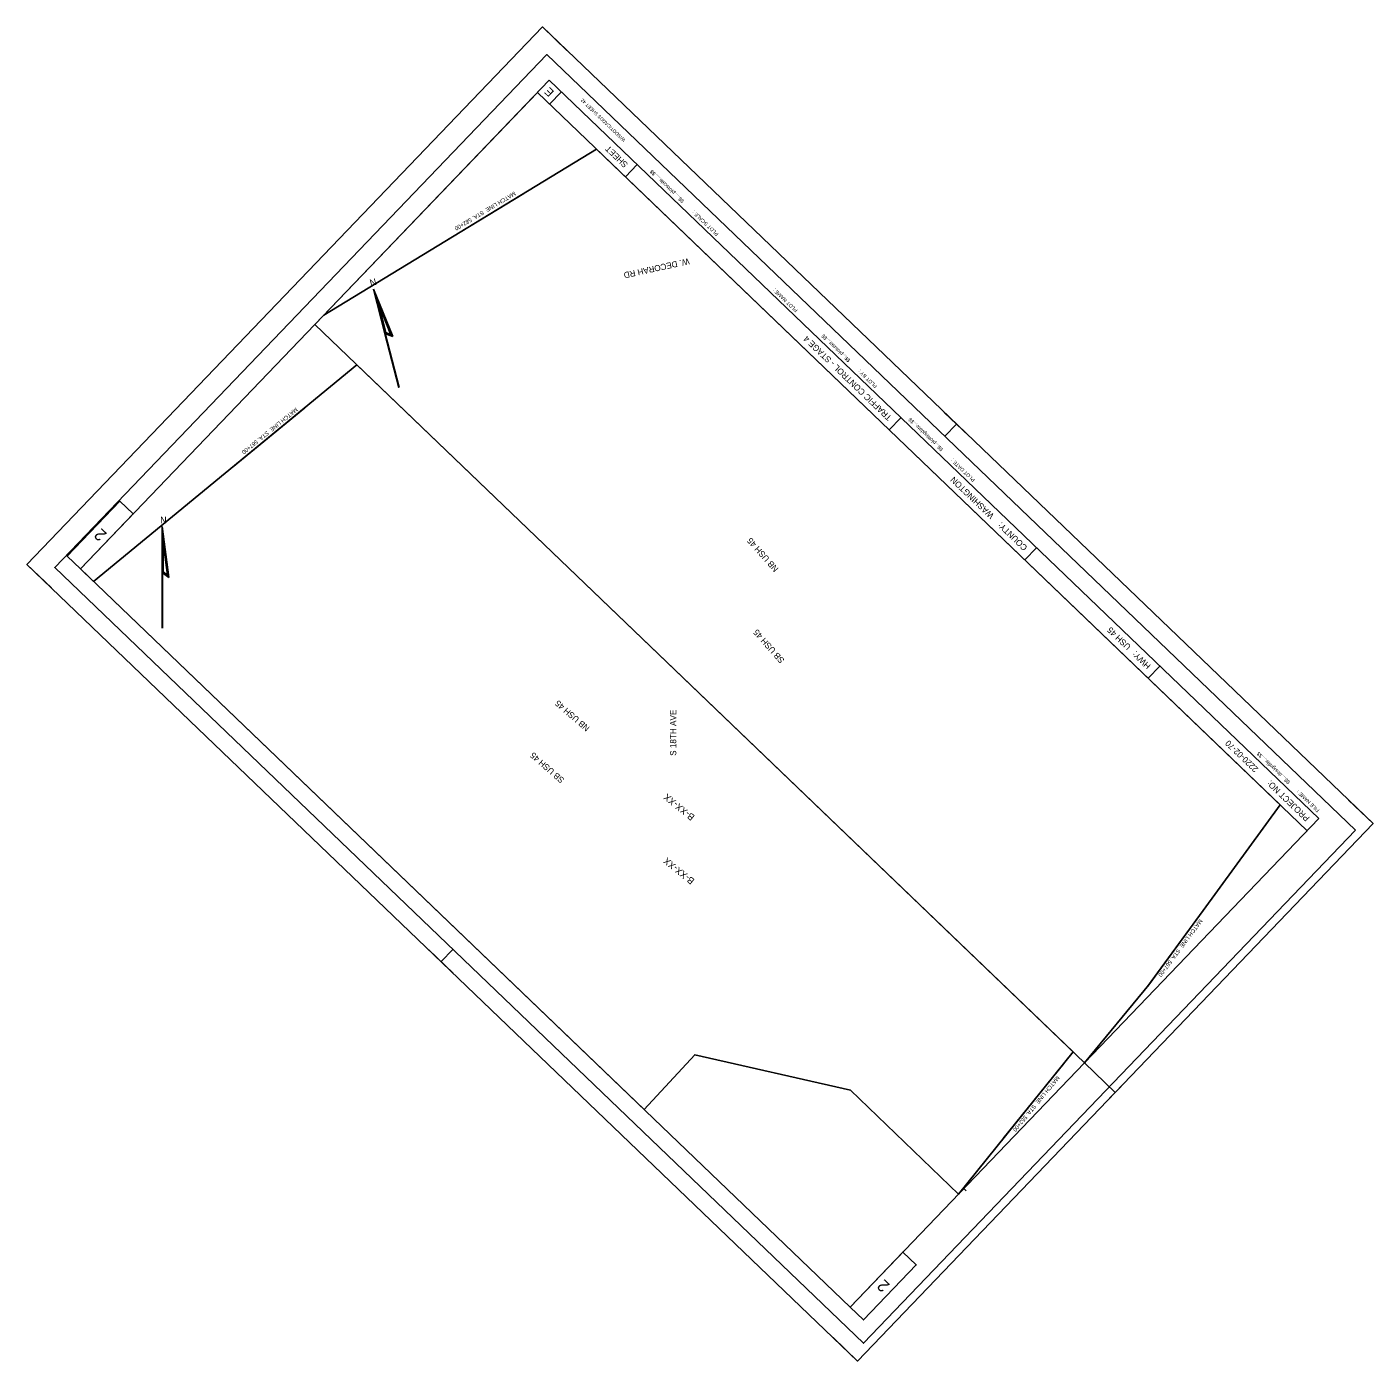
# Model space of a CAD drawing. Extents: x 356592 to 358580, y 177766 to 179737.
import ezdxf

# ---------------------------------------------------------------- set-up
doc = ezdxf.new("R2010")
doc.units = 0
for name, color, linetype in [('Default', 7, 'Continuous'), ('P_ALI_20', 7, 'Continuous'), ('P_ALI_200_Sta', 7, 'Continuous'), ('P_ALI_20_PIData', 7, 'Continuous'), ('P_ALI_20_Sta', 7, 'Continuous'), ('P_ALI_20_Tic', 7, 'Continuous'), ('P_ALI_50_Equation', 7, 'Continuous'), ('P_ALI_50_PIData', 7, 'Continuous'), ('P_ALI_50_Tic', 7, 'Continuous')]:
    doc.layers.add(name, color=color, linetype=linetype)

msp = doc.modelspace()

# ---------------------------------------------------------------- linework, layer by layer
msp.add_lwpolyline([(357818.7, 177766.2), (356591.8, 178942.9), (357353.2, 179736.8), (358580.1, 178560), (357818.7, 177766.2)])
at = {"layer": 'Default'}
for points in [[(358153.7, 178206.9), (358248.9, 178322), (358329.2, 178431.9), (358443, 178587.7), (357433, 179556.4), (357030.5, 179311.1), (357017.1, 179297.1)], [(358153.7, 178206.9), (358248.9, 178322), (358329.2, 178431.9), (358443, 178587.7), (357433, 179556.4), (357030.5, 179311.1), (357017.1, 179297.1)], [(358153.7, 178206.9), (358248.9, 178322), (358329.2, 178431.9), (358443, 178587.7), (357433, 179556.4), (357030.5, 179311.1), (357017.1, 179297.1)], [(358137, 178222.9), (357967.6, 178012.8), (357808, 178166.2), (357578.1, 178218.7), (357503.7, 178137.6), (356671, 178936.3), (356690.3, 178917.7), (357079.1, 179237.6)], [(358137, 178222.9), (357967.6, 178012.8), (357808, 178166.2), (357578.1, 178218.7), (357503.7, 178137.6), (356671, 178936.3), (356690.3, 178917.7), (357079.1, 179237.6)], [(358137, 178222.9), (357967.6, 178012.8), (357808, 178166.2), (357578.1, 178218.7), (357503.7, 178137.6), (356671, 178936.3), (356690.3, 178917.7), (357079.1, 179237.6)]]:
    msp.add_lwpolyline(points, close=True, dxfattribs=at)
at = {"layer": 'P_ALI_20'}
for p, q in [((357353.2, 179736.8), (357318.6, 179700.7)), ((357389.3, 179702.2), (357353.2, 179736.8)), ((357363.2, 179658), (356671, 178936.3)), ((358499.8, 178567.7), (357363.2, 179658)), ((358482.5, 178549.7), (357345.9, 179639.9)), ((357381.2, 179640.7), (357363.9, 179622.6)), ((357493.1, 179533.4), (357475.8, 179515.3)), ((358153.7, 178206.9), (357017.1, 179297.1)), ((357982.9, 179132.8), (357946.8, 179167.5)), ((357882.8, 179159.6), (357865.5, 179141.5)), ((357964.9, 179150.2), (357947.6, 179132.1)), ((356626.4, 178979), (356591.8, 178942.9)), ((358083.1, 178967.5), (358065.8, 178949.5)), ((356627.9, 178908.3), (356591.8, 178942.9)), ((357807.6, 177846), (356671, 178936.3)), ((358265.3, 178792.7), (358248, 178774.7)), ((358580.1, 178560), (358544, 178594.7)), ((358499.8, 178567.7), (357807.6, 177846)), ((358580.1, 178560), (358545.5, 178524)), ((357221.5, 178339), (357185.4, 178373.6)), ((357203.4, 178356.3), (357220.7, 178374.3)), ((358126.7, 178232.9), (358126.7, 178232.9)), ((358199.4, 178163.1), (358153.7, 178206.9)), ((358216.7, 178181.2), (358182.1, 178145.1)), ((357975.5, 178021.1), (357979.1, 178017.6)), ((357818.7, 177766.2), (357782.6, 177800.8)), ((357853.3, 177802.3), (357818.7, 177766.2))]:
    msp.add_line(p, q, dxfattribs=at)
for points in [[(356671, 178936.3), (356651.1, 178955.3), (356729, 179036.5), (356748.8, 179017.5)], [(357807.6, 177846), (357827.5, 177827), (357905.4, 177908.2), (357885.5, 177927.2)]]:
    msp.add_lwpolyline(points, close=True, dxfattribs=at)
at = {"layer": 'P_ALI_200_Sta'}
msp.add_lwpolyline([(357345.9, 179639.9), (357017.1, 179297.1)], dxfattribs=at)
at = {"layer": 'P_ALI_20_PIData'}
for p, q in [((357132.2, 179279.4), (357103.8, 179349.6)), ((357120.6, 179284.2), (357103.8, 179349.6)), ((357121.3, 179284.8), (357107.4, 179338.8)), ((357130.8, 179280.8), (357107.4, 179338.8)), ((357121.9, 179285.3), (357110.9, 179328.1)), ((357129.4, 179282.2), (357110.9, 179328.1)), ((357120.6, 179284.2), (357132.2, 179279.4)), ((357141.2, 179204.3), (357120.6, 179284.2)), ((357141.4, 179204.4), (357120.9, 179284.1)), ((357121.3, 179284.8), (357130.8, 179280.8)), ((357121.9, 179285.3), (357129.4, 179282.2)), ((356801.6, 178923.7), (356791.6, 178998.7)), ((356791.6, 178931.2), (356791.6, 178998.7)), ((356792.3, 178931.5), (356792.3, 178987.4)), ((356800.6, 178925.3), (356792.3, 178987.4)), ((356793.1, 178931.9), (356793.1, 178976.1)), ((356799.6, 178927), (356793.1, 178976.1)), ((356791.6, 178931.2), (356801.6, 178923.7)), ((356791.6, 178848.7), (356791.6, 178931.2)), ((356791.8, 178848.7), (356791.8, 178931)), ((356792.3, 178931.5), (356800.6, 178925.3)), ((356793.1, 178931.9), (356799.6, 178927))]:
    msp.add_line(p, q, dxfattribs=at)
for points in [[(357103.9, 179349.5), (357103.8, 179349.5)], [(356791.6, 178998.6), (356791.6, 178998.6)]]:
    msp.add_lwpolyline(points, dxfattribs=at)
at = {"layer": 'P_ALI_20_Tic'}
msp.add_lwpolyline([(357818.7, 177766.2), (356591.8, 178942.9), (357353.2, 179736.8), (358580.1, 178560)], close=True, dxfattribs=at)
at = {"layer": 'P_ALI_50_Equation'}
for p, q in [((357206.7, 179418.5), (357325.6, 179491)), ((356894.8, 179085.9), (357002.3, 179174.4)), ((358247, 178319.4), (358329.2, 178431.9)), ((358033.8, 178094.9), (358123.2, 178205.8))]:
    msp.add_line(p, q, dxfattribs=at)
at = {"layer": 'P_ALI_50_Tic'}
for points in [[(358580.1, 178560), (357353.2, 179736.8), (356591.8, 178942.9), (357818.7, 177766.2)], [(358554.1, 178550.3), (357359.7, 179695.9), (356632.9, 178938.1), (357827.3, 177792.5)]]:
    msp.add_lwpolyline(points, close=True, dxfattribs=at)

# ---------------------------------------------------------------- texts
at = {"layer": 'P_ALI_20'}
for s, height, p in [('E', 12, (357371.2, 179641.2)), ('WISDOT/CADDS SHEET 42', 5, (357476.3, 179570.3)), ('SHEET ', 9, (357480.3, 179534.5)), ('$$.....plotscale.....$$', 5.4, (357563.2, 179480)), ('PLOT SCALE : ', 5.4, (357613.8, 179431.4)), ('PLOT NAME :                      ', 5.4, (357730.6, 179318.7)), ('TRAFFIC CONTROL - STAGE 4', 9, (357870, 179160.7)), ('$$...plotuser...$$', 5.4, (357808.5, 179244.7)), ('PLOT BY :', 5.4, (357848.2, 179206.6)), ('$$...plottingdate...$$', 5.4, (357945.7, 179113.2)), ('PLOT DATE :', 5.4, (357992.6, 179068.2)), (' WASHINGTON', 9, (358023.4, 179013.6)), ('2', 17.5, (356710.8, 178988.2)), ('COUNTY:', 9, (358070.3, 178968.6)), (' USH 45', 9, (358225.5, 178819.8)), ('HWY:', 9, (358252.5, 178793.9)), (' 2220-02-70', 9, (358413.8, 178639.1)), ('$$....designfile....$$', 5.4, (358458.1, 178621.7)), ('PROJECT NO:', 9, (358487.1, 178568.9)), ('FILE NAME :', 5.4, (358501.4, 178580.1)), ('2', 17.5, (357867.3, 177878.9))]:
    msp.add_text(s, height=height, rotation=136.1942, dxfattribs=at).set_placement(p)
at = {"layer": 'P_ALI_20_PIData'}
msp.add_text('N', height=10, rotation=14.4143, dxfattribs=at).set_placement((357099.6, 179353.6))
msp.add_text('N', height=10, dxfattribs=at).set_placement((356788.5, 179003.6))
at = {"layer": 'P_ALI_20_Sta'}
for p in [(357579, 178571.4), (357578.7, 178477.1)]:
    msp.add_text('B-XX-XX', height=10, rotation=141.0664, dxfattribs=at).set_placement(p)
at = {"layer": 'P_ALI_50_PIData'}
for s, height, rotation, p in [('MATCH LINE  STA. 582+00', 6, 210.9487, (357311.5, 179494)), ('W. DECORAH RD', 9, 192.3331, (357569.2, 179395.3)), ('MATCH LINE  STA. 567+00', 6, 219.0327, (356988.8, 179174.9)), ('NB USH 45', 9, 131.4142, (357702.5, 178936.7)), ('SB USH 45', 9, 131.4142, (357711.3, 178801.8)), ('NB USH 45', 9, 139.0165, (357423.7, 178702.2)), ('S 18TH AVE', 9, 89.9965, (357550.8, 178660.1)), ('SB USH 45', 9, 138.8262, (357386.3, 178625.7)), ('MATCH LINE  STA. 567+00', 6, 233.447, (358323.9, 178419.6)), ('MATCH LINE  STA. 552+00', 6, 230.7122, (358113.1, 178188))]:
    msp.add_text(s, height=height, rotation=rotation, dxfattribs=at).set_placement(p)

doc.saveas('drawing.dxf')
